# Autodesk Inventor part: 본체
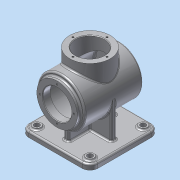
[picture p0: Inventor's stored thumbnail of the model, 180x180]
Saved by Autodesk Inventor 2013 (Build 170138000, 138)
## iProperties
Created: 2015-07
Part Number: 본체
Material: 알루미늄 6061
Document SubType Name: Modeling
Designer: dgall
Density: 2.71 g/cm^3
Mass: 1277.59 g
Surface Area: 1267.74 cm^2
Volume: 471.434 cm^3
Author: dgall
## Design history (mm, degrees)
sketch "스케치1"
  geometry: L1 (-65, 65)-(65, 65); L2 (65, 65)-(65, -65); L3 (65, -65)-(-65, -65); L4 (-65, -65)-(-65, 65); 5 further points
  constraints: 8 end point, 4 midpoint, 2 horizontal alignment, 2 parallel, 2 vertical alignment, 1 horizontal, 1 perpendicular
  dimensions: "d0" = 130 distance of L1.start L1.end; "d2" = 130 distance of L1.end L2.end
extrude "돌출1" new body sketch "스케치1" distance "d3" = 10; taper "d4" = 0 deg
node "작업 평면1"
sketch "스케치3"
  geometry: L1 (0, -65)-(0, 65) reference; C1 r 45 at (78, 0); 2 further points
  constraints: 1 centre point, 1 horizontal alignment, 1 midpoint
  dimensions: "d14" = 78 distance from line of C1.centre L1; "d15" = 90 diameter of C1
extrude "돌출2" join sketch "스케치3" distance "d16" = 110; taper "d17" = 0 deg
sketch "스케치4"
  geometry: C1 r 45 at (0, 0) reference; C2 r 38 at (0, 0); 1 further point
  constraints: 1 centre point, 1 coincident
  dimensions: "d18" = 76 diameter of C2
extrude "돌출3" join sketch "스케치4" distance "d20" = 7; taper "d21" = 0 deg
sketch "스케치5"
  geometry: L1 (-55, 123)-(55, 123) reference; L2 (55, 123)-(55, 33) reference; L3 (55, 33)-(-55, 33) reference; L4 (-55, 33)-(-55, 40) reference; L5 (-55, 40)-(-62, 40) reference; L6 (-62, 40)-(-62, 116) reference; L7 (-62, 116)-(-55, 116) reference; L8 (-55, 116)-(-55, 123) reference; L9 (65, 10)-(65, 0) reference; L10 (65, 0)-(-65, 0) reference; L11 (-65, 0)-(-65, 10) reference; L12 (-65, 10)-(65, 10) reference; L13 (-62, 78)-(55, 78); L14 (-62, 105)-(-48, 105); L15 (-48, 105)-(-48, 118); L16 (-48, 118)-(48, 118); L17 (48, 118)-(48, 78); L18 (-62, 105)-(-62, 78); 1 further point
  constraints: 12 end point, 3 perpendicular, 2 midpoint, 2 point on line, 1 collinear, 1 parallel
  dimensions: "d22" = 14 distance of L14.start L14.end; "d24" = 54 diameter of L14 L13; "d25" = 96 distance of L15.end L16.end; "d26" = 80 diameter of L16 L13
revolve "회전1" sketch "스케치5" stored, may be unused: angle "d27" = 90 deg
sketch "스케치6"
  geometry: L1 (-5, 45)-(5, 45); L2 (5, 45)-(5, -45); L3 (5, -45)-(-5, -45); L4 (-5, -45)-(-5, 45); L5 (-45, 5)-(45, 5); L6 (45, 5)-(45, -5); L7 (45, -5)-(-45, -5); L8 (-45, -5)-(-45, 5); 8 further points
  constraints: 16 end point, 7 midpoint, 4 parallel, 4 vertical alignment, 3 horizontal alignment, 2 horizontal, 2 perpendicular
  dimensions: "d28" = 10 distance of L1.start L1.end; "d30" = 90 distance between parallel lines of L3 L1; "d31" = 90 distance of L6.end L7.end; "d32" = 10 distance between parallel lines of L7 L5
extrude "돌출4" join sketch "스케치6" stored distance "d33" = 7; taper "d34" = 0 deg
node "작업 평면2"
sketch "스케치7"
  geometry: C1 r 38 at (0, 0); C2 r 27 at (0, 0); 1 further point
  constraints: 2 centre point, 2 coincident
  dimensions: "d36" = 76 diameter of C1; "d38" = 54 diameter of C2
extrude "돌출5" join sketch "스케치7" stored distance "d39" = 7; taper "d40" = 0 deg
extrude "돌출6" cut sketch "스케치7" stored distance "d41" = 7; taper "d42" = 0 deg
sketch "스케치8"
  geometry: L1 (-45, -5)-(-45, 5) reference; L2 (-45, 5)-(-5, 5) reference; L3 (-5, 5)-(-5, 45) reference; L4 (-5, 45)-(5, 45) reference; L5 (5, 45)-(5, 5) reference; L6 (5, 5)-(45, 5) reference; L7 (45, 5)-(45, -5) reference; L8 (45, -5)-(5, -5) reference; L9 (5, -5)-(5, -45) reference; L10 (5, -45)-(-5, -45) reference; L11 (-5, -45)-(-5, -5) reference; L12 (-5, -5)-(-45, -5) reference; L13 (-65, -65)-(-65, 65) reference; L14 (-65, 65)-(65, 65) reference; L15 (65, 65)-(65, -65) reference; L16 (65, -65)-(-65, -65) reference; C1 r 7.5 at (-50, 50); 1 further point
  constraints: 1 centre point
  dimensions: "d43" = 15 diameter of C1; "d46" = 50 horizontal distance of C1.centre point (0, 0); "d47" = 50 horizontal distance of point (0, 0) C1.centre
extrude "돌출7" join sketch "스케치8" distance "d48" = 3; taper "d49" = 0 deg
sketch "스케치9"
  geometry: C1 r 7.5 at (0, 0) reference; C2 r 5 at (0, 0); 1 further point
  constraints: 1 centre point, 1 coincident
  dimensions: "d50" = 10 diameter of C2
extrude "돌출8" cut sketch "스케치9" stored distance "d52" = 3; taper "d53" = 0 deg
sketch "스케치10" dims "d60" = 64
  geometry: C1 r 27 at (0, 0) reference; C2 r 38 at (0, 0) reference; 3 further points
  constraints: 2 vertical alignment, 1 coincident, 2 other
hole "구멍1" sketch "스케치10" at (0, 32) diameter "d62" = 3.242; stored, may be unused: countersink angle "d66" = 90 deg, drill point angle "d68" = 118 deg; dims "d63" = 8, "d64" = 4, "d65" = 2, "d67" = 10
sketch "스케치11" dims "d72" = 64
  geometry: C1 r 27 at (0, 0) reference; C2 r 38 at (0, 0) reference; 2 further points
  constraints: 2 vertical alignment, 1 coincident, 2 other
hole "구멍2" sketch "스케치11" at (0, 32) diameter "d74" = 3.242; stored, may be unused: countersink angle "d78" = 90 deg, drill point angle "d80" = 118 deg; dims "d75" = 8, "d76" = 4, "d77" = 2, "d79" = 10
sketch "스케치12"
  geometry: C1 r 45 at (0, 0) reference; 2 further points
  constraints: 1 coincident, 1 other
feature "엠보싱1" sketch "스케치12" dims "d0" = 130, "d2" = 130, "d84" = 0.5, "d85" = 0
fillet "모깎기1" dims "d86" = 15
fillet "모깎기2" dims "d87" = 3
fillet "모깎기3" dims "d88" = 3
chamfer "모따기1" distance "d89" = 1; stored, may be unused: second distance "d90" = 2, angle "d91" = 45 deg
fillet "모깎기5" dims "d93" = 3
node "솔리드1"
pattern_linear "직사각형 패턴1"
pattern_circular "원형 패턴1" dims angle "d70" = 360 deg
pattern_circular "원형 패턴2" dims angle "d82" = 360 deg
node "절단 모서리 투영1"
node "절단 모서리 투영2"
other parameters: "d13" = -55
